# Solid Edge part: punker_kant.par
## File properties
Author: Blackblade
Template: Normal.par
Last saved by: Blackblade
Revision: 21
Application: Solid Edge
Accuracy: 0.990
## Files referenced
..\baltic70_assembly_test.asm
\HK KOLLEDZ\III.kursus\Solid edge\baltic70_assembly_test.asm
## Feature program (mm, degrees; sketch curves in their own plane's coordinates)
sketch for "unnamed Protrusion 1" plane through (12.7222, 0, -8.6126) normal (0, -1, 0) x-axis (1, 0, 0)
  line (-68.3447, 8.6126) -> (-68.3447, 9.6126)
  line (-68.3447, 9.6126) -> (-56.5549, 9.6126)
extrude "unnamed Protrusion 1" add finite 171.8154 symmetric
sketch for "valja_loige" plane through (0, 0, 0) normal (0, 0, 1) x-axis (1, 0, 0)
  arc centre (67.9255, -577.5355) radius 650 from (-116.8807, 45.6392) to (366.9641, -0.4082) cw
  arc centre (67.9255, 576.7191) radius 650 from (-116.8807, -46.4556) to (366.9641, -0.4082) ccw
  arc centre (-50.426, -0.4082) radius 80.8492 from (-131.2752, -0.4082) to (-116.8807, -46.4556) ccw
  arc centre (-50.426, -0.4082) radius 80.8492 from (-131.2752, -0.4082) to (-116.8807, 45.6392) cw
extrude "valja_loige" cut finite 70 along +normal
fillet "Round_2" radius 50
sketch used by "ExtrudedCutout_9" plane through (0, 0, 0) normal (0, 0, 1) x-axis (1, 0, 0)
extrude "ExtrudedCutout_9" cut finite 70 along +normal
sketch used by "rurgad_maha" plane through (29.3775, -0.4082, 0) normal (0, 0, -1) x-axis (0.998209, 0.05982, 0)
extrude "rurgad_maha" cut finite 70 along -normal
thinwall "Thinwall_4"  Thickness = 1 mm
sketch used by "ExtrudedCutout_13" plane through (0, 0, 0) normal (0, -1, 0) x-axis (1, 0, 0)
extrude "ExtrudedCutout_13" cut finite 252.6226 symmetric
sketch used by "tooli_ase" plane through (28.737, -0.3279, 1) normal (0, 0, 1) x-axis (0.998209, -0.05982, 0)
  circle centre (26.4999, 1.9166) radius 12.5
extrude "tooli_ase" add finite 0.1 along +normal
sketch for "antenni_alus" plane through (0, 0, 69) normal (0, 0, 1) x-axis (1, 0, 0)
  circle centre (16.6941, 0) radius 2.305
extrude "antenni_alus" add finite 1.2 along +normal
sketch for "ExtrudedCutout_14" plane through (0, 0, 0) normal (0, 0, 1) x-axis (1, 0, 0)
  line (29.7956, -40.0908) -> (-20.2044, -40.0908)
  line (-20.2044, -40.0908) -> (-20.2044, -0.0908)
  line (-20.2044, -0.0908) -> (29.7956, -0.0908)
  line (29.7956, -0.0908) -> (29.7956, -40.0908)
extrude "ExtrudedCutout_14" cut finite 1 along +normal
logasc func "Lip_Groove_1"  LipOrGrooveWidth = 0.5 mm; LipOrGrooveHeight = 0.5 mm
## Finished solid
Body 1: solid body, 45 faces, 124 edges, 80 vertices.
  Faces by surface: plane 25, cylinder 12, blend 8
  Edges by curve: line 60, intersection 47, circle 11, ellipse 6
Bounding box of the edges (mm; curved faces can reach further): 170.000 x 142.184 x 70.200, from (-55.6225, -71.3812, 0) to (114.3775, 70.8026, 70.2).
Cylindrical faces by radius (mm): R2.305 x1, R12.5 x1, R70 x1, R314.3388 x1, R315.3388 x2, R648 x3, R649 x3
Planar faces by outward normal: +x 4, +y 2, +z 4, -x 3, -y 2, -z 2, oblique 8
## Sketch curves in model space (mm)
line (29.7956, -0.0908, 0) -> (29.7956, -40.0908, 0)
line (29.7956, -40.0908, 0) -> (-20.2044, -40.0908, 0)
line (-20.2044, -40.0908, 0) -> (-20.2044, -0.0908, 0)
line (-20.2044, -0.0908, 0) -> (29.7956, -0.0908, 0)
circle centre (16.6941, 0, 69) radius 2.305
line (63.0788, 0, 25.2688) -> (63.0788, 0, 60.3721)
arc centre (18.5138, 0, -251.8018) radius 315.3388 from (63.0788, 0, 60.3721) through (82.283, 0, 57.0219) to (101.2435, 0, 52.4914)
line (108.0549, 0, 25.2688) -> (101.2435, 0, 52.4914)
line (108.0549, 0, 25.2688) -> (63.0788, 0, 25.2688)
line (114.3775, 70.8026, 0) -> (114.3775, -71.1868, 0)
arc centre (80.6302, -577.3194, 0) radius 649 from (-55.6225, 57.2168, 0) through (28.9293, 69.618, 0) to (114.3775, 70.8026, 0)
line (-55.6225, 57.2168, 0) -> (-55.6225, -57.6011, 0)
arc centre (80.6302, 576.9351, 0) radius 649 from (-55.6225, -57.6011, 0) through (28.9293, -70.0023, 0) to (114.3775, -71.1868, 0)
line (92.0671, 69.4656, 25.2688) -> (63.0788, 67.7284, 25.2688)
spline (108.0549, 66.9618, 25.2688) -> (100.0757, 68.3589, 25.2688) -> (92.0671, 69.4656, 25.2688)
line (108.0549, -67.7782, 25.2688) -> (108.0549, 66.9618, 25.2688)
spline (92.0671, -70.2819, 25.2688) -> (100.0757, -69.1753, 25.2688) -> (108.0549, -67.7782, 25.2688)
line (63.0788, -68.5447, 25.2688) -> (92.0671, -70.2819, 25.2688)
line (114.3775, 70.8026, 0) -> (114.3775, -71.6189, 0)
line (114.3775, -71.6189, 0) -> (-55.6225, -61.4313, 0)
line (-55.6225, -61.4313, 0) -> (-55.6225, 60.6149, 0)
line (-55.6225, 60.6149, 0) -> (114.3775, 70.8026, 0)
circle centre (55.3041, 0, 1) radius 12.5
arc centre (67.9255, 576.7191, 0) radius 650 from (-116.8807, -46.4556, 0) through (129.5076, -70.3571, 0) to (366.9641, -0.4082, 0)
arc centre (-50.426, -0.4082, 0) radius 80.8492 from (-131.2752, -0.4082, 0) through (-127.5927, -24.5306, 0) to (-116.8807, -46.4556, 0)
arc centre (-50.426, -0.4082, 0) radius 80.8492 from (-131.2752, -0.4082, 0) through (-127.5927, 23.7142, 0) to (-116.8807, 45.6392, 0)
arc centre (67.9255, -577.5355, 0) radius 650 from (-116.8807, 45.6392, 0) through (129.5076, 69.5407, 0) to (366.9641, -0.4082, 0)
line (114.3775, 0, 0) -> (99.8137, 0, 58.2056)
arc centre (14.3775, 0, -245.3388) radius 315.3388 from (14.3775, 0, 70) through (57.5007, 0, 67.0375) to (99.8137, 0, 58.2056)
arc centre (-55.6225, 0, 70) radius 70 from (-43.8326, 0, 1) through (-2.1188, 0, 24.8629) to (14.3775, 0, 70)
line (-55.6225, 0, 1) -> (-43.8326, 0, 1)
line (-55.6225, 0, 0) -> (-55.6225, 0, 1)
line (14.3775, 0, 0) -> (-55.6225, 0, 0)
line (14.3775, 0, 0) -> (114.3775, 0, 0)
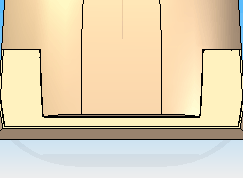
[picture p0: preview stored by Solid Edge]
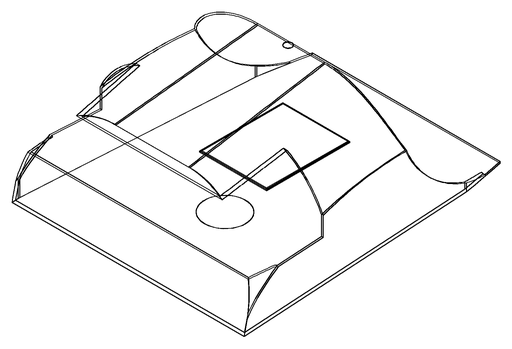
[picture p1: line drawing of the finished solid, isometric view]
